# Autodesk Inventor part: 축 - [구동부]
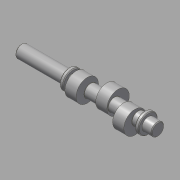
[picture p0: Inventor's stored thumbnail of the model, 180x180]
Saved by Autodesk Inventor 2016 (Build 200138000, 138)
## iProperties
Company: 한국ATC센터
Created: 2014-08
Part Number: 축 - [구동부]
Document SubType Name: Modeling
Designer: KYOUNG IL JANG
Density: 7.86 g/cm^3
Material: 강철, 연강
Appearance: 강철
Mass: 516.584 g
Surface Area: 162.516 cm^2
Volume: 65.7231 cm^3
Author: KYOUNG IL JANG
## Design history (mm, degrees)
sketch "스케치1"
  geometry: L1 (-91.5, 0)-(91.5, 0); L2 (-91.5, 0)-(-91.5, 8.5); L3 (-91.5, 8.5)-(-27.5, 8.5); L4 (-27.5, 8.5)-(-27.5, 13); L5 (-27.5, 13)-(-22.5, 13); L6 (-22.5, 13)-(-22.5, 8.5); L7 (-22.5, 8.5)-(73.5, 8.5); L8 (73.5, 8.5)-(73.5, 13); L9 (73.5, 13)-(78.5, 13); L10 (78.5, 13)-(78.5, 8.5); L11 (78.5, 8.5)-(91.5, 8.5); L12 (91.5, 8.5)-(91.5, 0); 2 further points
  constraints: 24 end point, 5 parallel, 1 coincident, 1 horizontal, 1 midpoint, 1 perpendicular
  dimensions: "d0" = 183 distance of L1.start L1.end (derived); "d2" = 17 diameter of L3 L1; "d3" = 26 diameter of L5 L1; "d4" = 17 diameter of L7 L1; "d5" = 26 diameter of L9 L1; "d6" = 17 diameter of L11 L1; "d7" = 5 distance of L8.end L9.end; "d8" = 5 distance of L4.end L5.end; "d10" = 64 distance of L2.end L3.end; "d11" = 13 distance of L10.end L11.end; "d35" = 96 distance between parallel lines of L8 L6
revolve "회전1" sketch "스케치1" stored, may be unused: angle "d12" = 90 deg
node "작업 평면7"
sketch "스케치6"
  geometry: C1 r 15 at (0, 5); 1 further point
  constraints: 1 centre point, 1 vertical alignment
  dimensions: "d37" = 30 diameter of C1; "d38" = 5 distance of C1.centre point (0, 0)
extrude "돌출4" join sketch "스케치6" stored distance "d33" = 15; taper "d34" = 0 deg
node "작업 평면8"
sketch "스케치7"
  geometry: L1 (0, 0)-(-6.5, -11.258); L2 (0, 0)-(13, 0); C1 r 15 at (-2.5, -4.33); A1 r 13 centre (0, 0) between (-6.5, -11.258) and (13, 0) reference; 1 further point
  constraints: 4 end point, 2 point on circle, 1 centre point, 1 horizontal, 1 point on line
  dimensions: "d40" = 120 deg angle of L1 L2; "d41" = 30 diameter of C1; "d42" = 5 distance of point (0, 0) C1.centre
extrude "돌출5" join sketch "스케치7" stored distance "d43" = 15; taper "d44" = 0 deg
node "작업 평면9"
sketch "스케치8"
  geometry: L1 (0, 0)-(4.25, -7.361); L2 (0, 0)-(-8.5, 0); C1 r 15 at (2.5, -4.33); A1 r 8.5 centre (0, 0) between (4.25, -7.361) and (-8.5, 0) reference; 1 further point
  constraints: 4 end point, 2 point on circle, 1 centre point, 1 horizontal, 1 point on line
  dimensions: "d46" = 120 deg angle of L1 L2; "d47" = 30 diameter of C1; "d48" = 5 distance of point (0, 0) C1.centre
extrude "돌출6" join sketch "스케치8" stored distance "d49" = 15; taper "d50" = 0 deg
node "작업 평면3"
sketch "스케치5"
  geometry: L1 (32, 8.5)-(32, -8.5) reference; L2 (27.5, -2.5)-(14.5, -2.5); L3 (14.5, 2.5)-(27.5, 2.5); A1 r 2.5 centre (14.5, 0) between (14.5, 2.5) and (14.5, -2.5); A2 r 2.5 centre (27.5, 0) between (27.5, -2.5) and (27.5, 2.5); 4 further points
  constraints: 4 end point, 4 point on circle, 4 tangent, 2 centre point, 2 point on line, 1 horizontal alignment, 1 midpoint, 1 parallel, 1 perpendicular
  dimensions: "d23" = 5 distance between parallel lines of L3 L2; "d36" = 20 dimension on A1 L1; "d52" = 2 distance edge to line of A2 L1
extrude "돌출3" cut sketch "스케치5" distance "d25" = 3; taper "d26" = 0 deg
chamfer "모따기1" distance "d27" = 1; stored, may be unused: second distance "d28" = 2, angle "d29" = 45 deg
fillet "모깎기1" dims "d51" = 0.3
chamfer "모따기2" distance "d53" = 1; stored, may be unused: second distance "d54" = 2, angle "d55" = 45 deg
node "작업 평면10"
node "솔리드1"
other parameters: "d39" = -32, "d45" = 32
